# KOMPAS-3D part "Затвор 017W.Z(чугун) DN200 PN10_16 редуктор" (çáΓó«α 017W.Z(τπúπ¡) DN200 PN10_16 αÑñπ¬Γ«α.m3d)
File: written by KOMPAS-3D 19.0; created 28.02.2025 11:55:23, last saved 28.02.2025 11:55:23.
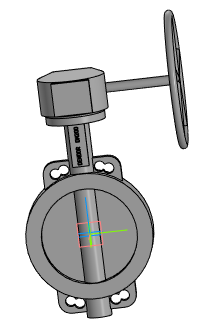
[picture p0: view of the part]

Document properties: Автор: Евгений; Полное имя файла: Затвор 017W.Z(чугун) DN200 PN10_16 редуктор.m3d

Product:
- Part/product: Затвор 017W.Z(чугун) DN200 PN10_16 редуктор
    Масса: 37.1379
  - Component [detail]: Редуктор DN200-250(250)  | Масса: 14.4939; source file: ..\1.3 Тип 017W.ZS Затвор дисковый поворотный Межфланцевый\Редуктор.z DN200-250(250).m3d
  - Component [detail]: Затвор 017W.Z(чугун) DN200 PN10_16 под ЭП  | Масса: 22.644; source file: Затвор 017W.Z(чугун) DN200 PN10_16 под ЭП.m3d

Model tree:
1. Элемент выдавливания:2  (with: Элемент вращения:1, Элемент выдавливания:7, Элемент выдавливания:8)

Referenced files in E:\Dendor Работа Сачек\3D для проекитирвщиков\1.3 Тип 017W.ZS Затвор дисковый поворотный Межфланцевый\: Редуктор.z DN200-250(250).m3d
Referenced files in E:\Dendor Работа Сачек\3D для проекитирвщиков\1.4 Тип 017W.Z чугун Затвор дисковый поворотный Межфланцевый\: Затвор 017W.Z(чугун) DN200 PN10_16 под ЭП.m3d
